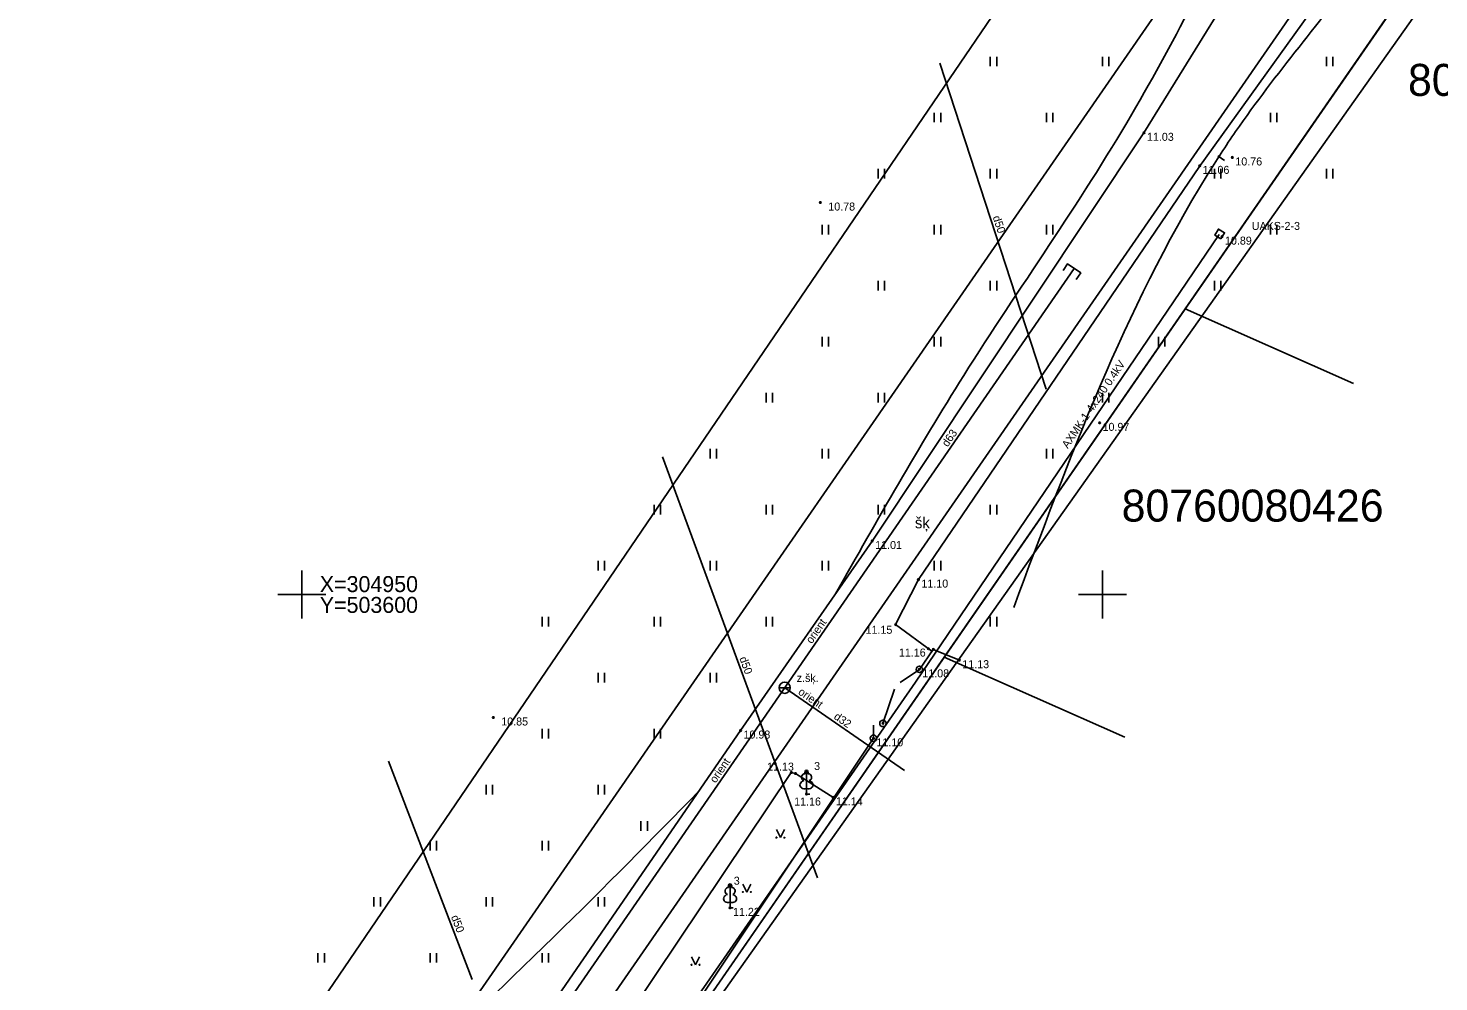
# Model space of a CAD drawing. Extents: x 503353 to 504004, y 304662 to 305049.
# Drawn here: x 503582.9 to 503671, y 304925.8 to 304985.4 of the extents above; entities that cross this region are included whole.
import ezdxf

# ---------------------------------------------------------------- set-up
doc = ezdxf.new("R2010")
doc.units = 0
for name, color, linetype in [('24', 7, 'Continuous'), ('25', 7, 'Continuous'), ('59', 7, 'Continuous'), ('APGR_SARK_####_####_#', 7, 'Continuous'), ('CELI_CAPM_####_####_#', 7, 'Continuous'), ('CELI_CMAL_####_####_#', 7, 'Continuous'), ('CELI_CSEG_####_TKST_#', 7, 'Continuous'), ('DREN_VADP_####_####_#', 7, 'Continuous'), ('DREN_VADP_####_TKST_#', 7, 'Continuous'), ('ELEK_ELEM_####_####_#', 7, 'Continuous'), ('ELEK_VADP_ZSPR_####_#', 7, 'Continuous'), ('ELEK_VADP_ZSPR_TKST_#', 7, 'Continuous'), ('GEOD_ELEM_####_####_#', 7, 'Continuous'), ('GEOD_KORD_####_TKST_#', 7, 'Continuous'), ('NORB_ELEM_####_####_#', 7, 'Continuous'), ('NORB_ZOGS_BARJ_####_#', 7, 'Continuous'), ('NORB_ZOGS_KBST_####_#', 7, 'Continuous'), ('NORB_ZOGS_ZSTP_####_#', 7, 'Continuous'), ('RAMI_UZMR_####_####_#', 7, 'Continuous'), ('RELJ_AATZ_####_TKST_#', 7, 'Continuous'), ('RELJ_ELEM_####_####_#', 7, 'Continuous'), ('RELJ_HORZ_PAMT_####_#', 7, 'Continuous'), ('TERT_DIAM_####_TKST_#', 7, 'Continuous'), ('TERT_ELEM_####_####_#', 7, 'Continuous'), ('UDTK_ELEM_####_####_#', 7, 'Continuous'), ('UDTK_ELEM_####_TKST_#', 7, 'Continuous'), ('UDTK_VADP_UDEN_####_#', 7, 'Continuous'), ('UDTK_VADP_UDEN_TKST_#', 7, 'Continuous')]:
    doc.layers.add(name, color=color, linetype=linetype)

msp = doc.modelspace()

# ---------------------------------------------------------------- linework, layer by layer
at = {"layer": '24'}
for p, q in [((503655.169, 304967.847), (503676.504, 304998.703)), ((503640.119, 304946.083), (503655.169, 304967.847)), ((503665.697, 304963.177), (503655.169, 304967.847)), ((503621.894, 304919.725), (503640.119, 304946.083)), ((503640.119, 304946.083), (503651.401, 304941.078))]:
    msp.add_line(p, q, dxfattribs=at)
at = {"layer": '25'}
msp.add_line((503672.032, 305001.026), (503595.592, 304890.48), dxfattribs=at)
at = {"layer": 'APGR_SARK_####_####_#'}
for p, q in [((503595.509, 304902.665), (503658.316, 304993.498)), ((503669.455, 304988.508), (503606.367, 304897.269))]:
    msp.add_line(p, q, dxfattribs=at)
at = {"layer": 'CELI_CAPM_####_####_#'}
msp.add_lwpolyline([(503630.569, 304938.881), (503619.284, 304922.036)], dxfattribs=at)
at = {"layer": 'CELI_CMAL_####_####_#'}
for points in [[(503605.515, 304909.352), (503607.775, 304912.97), (503627.397, 304941.5), (503635.622, 304953.341), (503652.6, 304978.844), (503660.954, 304992.392), (503665.471, 305000.768), (503665.873, 305004.349)], [(503674.743, 305000.37), (503671.232, 304998.583), (503665.707, 304990.166), (503656.075, 304976.73), (503638.511, 304950.933)], [(503638.511, 304950.933), (503637.086, 304948.12), (503639.351, 304946.45)], [(503630.569, 304938.881), (503630.828, 304938.817), (503633.22, 304937.294)]]:
    msp.add_lwpolyline(points, dxfattribs=at)
at = {"layer": 'DREN_VADP_####_####_#'}
for p, q in [((503646.495, 304962.83), (503639.848, 304983.193)), ((503632.207, 304932.288), (503622.519, 304958.6)), ((503610.64, 304925.952), (503605.409, 304939.594))]:
    msp.add_line(p, q, dxfattribs=at)
at = {"layer": 'ELEK_ELEM_####_####_#'}
msp.add_lwpolyline([(503657.407, 304972.221), (503657.024, 304972.452), (503657.251, 304972.829), (503657.634, 304972.598)], close=True, dxfattribs=at)
at = {"layer": 'ELEK_VADP_ZSPR_####_#'}
msp.add_lwpolyline([(503657.3, 304972.484), (503638.321, 304944.533), (503622.227, 304921.298)], dxfattribs=at)
at = {"layer": 'GEOD_ELEM_####_####_#'}
for p, q in [((503600, 304951.5), (503600, 304950)), ((503600, 304951.5), (503600, 304950)), ((503650, 304951.5), (503650, 304950)), ((503650, 304951.5), (503650, 304950)), ((503598.5, 304950), (503600, 304950)), ((503598.5, 304950), (503600, 304950)), ((503600, 304950), (503600, 304948.5)), ((503600, 304950), (503601.5, 304950)), ((503600, 304950), (503600, 304948.5)), ((503600, 304950), (503601.5, 304950)), ((503648.5, 304950), (503650, 304950)), ((503648.5, 304950), (503650, 304950)), ((503650, 304950), (503650, 304948.5)), ((503650, 304950), (503651.5, 304950)), ((503650, 304950), (503650, 304948.5)), ((503650, 304950), (503651.5, 304950))]:
    msp.add_line(p, q, dxfattribs=at)
at = {"layer": 'NORB_ELEM_####_####_#'}
for centre in [(503638.568, 304945.324), (503636.292, 304941.947), (503635.703, 304941.016)]:
    msp.add_circle(centre, 0.202, dxfattribs=at)
at = {"layer": 'NORB_ZOGS_BARJ_####_#'}
for p, q in [((503638.568, 304945.324), (503637.376, 304944.51)), ((503636.292, 304941.947), (503637.005, 304944.076)), ((503635.703, 304941.016), (503635.703, 304941.839))]:
    msp.add_line(p, q, dxfattribs=at)
at = {"layer": 'NORB_ZOGS_KBST_####_#'}
for points in [[(503639.437, 304946.574), (503638.568, 304945.324)], [(503635.703, 304941.016), (503621.748, 304920.094)]]:
    msp.add_lwpolyline(points, dxfattribs=at)
at = {"layer": 'NORB_ZOGS_ZSTP_####_#'}
msp.add_lwpolyline([(503641.066, 304945.897), (503639.437, 304946.574)], dxfattribs=at)
at = {"layer": 'RAMI_UZMR_####_####_#'}
msp.add_lwpolyline([(503825.923, 304784.828), (503697.433, 304847.709), (503608.51, 304889.842), (503606.524, 304897.202), (503679.244, 304999.942), (503684.897, 305009.76), (503666.777, 305017.939), (503656.134, 304996.39), (503644.103, 304987.6), (503600.987, 304924.263), (503587.985, 304916.668), (503422.237, 304989.372), (503408.615, 305023.495), (503368.776, 305020.183)], dxfattribs=at)
at = {"layer": 'RELJ_ELEM_####_####_#'}
for centre in [(503652.6, 304978.844), (503658.121, 304977.306), (503656.075, 304976.78), (503632.38, 304974.489), (503657.474, 304972.36), (503649.826, 304960.724), (503635.622, 304953.341), (503638.511, 304950.933), (503637.086, 304948.12), (503639.132, 304946.611), (503639.437, 304946.574), (503641.066, 304945.897), (503638.568, 304945.324), (503611.951, 304942.316), (503627.397, 304941.5), (503636.292, 304941.947), (503635.703, 304941.016), (503630.569, 304938.881), (503630.828, 304938.817), (503631.518, 304937.533), (503633.168, 304937.327), (503626.742, 304930.423)]:
    msp.add_circle(centre, 0.05, dxfattribs=at)
at = {"layer": 'RELJ_HORZ_PAMT_####_#'}
msp.add_line((503657.638, 304977.125), (503657.22, 304977.398), dxfattribs=at)
for points in [[(503633.337, 304950.051), (503641.34, 304963.681), (503651.833, 304980), (503659.721, 304994.671), (503662.005, 305000.088), (503662.005, 305002.22), (503658.32, 305004.641)], [(503679.623, 304997.028), (503675.778, 304998.226), (503671.921, 304996.503), (503671.06, 304995.689), (503666.309, 304989.46), (503658.324, 304978.924), (503656.549, 304976.193), (503644.463, 304949.187)], [(503653.856, 304861.224), (503644.002, 304865.053), (503628.506, 304872.58), (503611.965, 304878.986), (503602.441, 304884.188), (503591.366, 304889.404), (503588.291, 304891.572), (503604.352, 304917.909), (503624.778, 304937.692)]]:
    msp.add_spline(points, degree=3, dxfattribs=at)
at = {"layer": 'TERT_ELEM_####_####_#'}
for p, q in [((503643, 304983), (503643, 304983.6)), ((503643.4, 304983), (503643.4, 304983.6)), ((503650, 304983), (503650, 304983.6)), ((503650.4, 304983), (503650.4, 304983.6)), ((503664, 304983), (503664, 304983.6)), ((503664.4, 304983), (503664.4, 304983.6)), ((503639.5, 304979.5), (503639.5, 304980.1)), ((503639.9, 304979.5), (503639.9, 304980.1)), ((503646.5, 304979.5), (503646.5, 304980.1)), ((503646.9, 304979.5), (503646.9, 304980.1)), ((503660.5, 304979.5), (503660.5, 304980.1)), ((503660.9, 304979.5), (503660.9, 304980.1)), ((503636, 304976), (503636, 304976.6)), ((503636.4, 304976), (503636.4, 304976.6)), ((503643, 304976), (503643, 304976.6)), ((503643.4, 304976), (503643.4, 304976.6)), ((503657, 304976), (503657, 304976.6)), ((503657.4, 304976), (503657.4, 304976.6)), ((503664, 304976), (503664, 304976.6)), ((503664.4, 304976), (503664.4, 304976.6)), ((503632.5, 304972.5), (503632.5, 304973.1)), ((503632.9, 304972.5), (503632.9, 304973.1)), ((503639.5, 304972.5), (503639.5, 304973.1)), ((503639.9, 304972.5), (503639.9, 304973.1)), ((503646.5, 304972.5), (503646.5, 304973.1)), ((503646.9, 304972.5), (503646.9, 304973.1)), ((503660.5, 304972.5), (503660.5, 304973.1)), ((503660.9, 304972.5), (503660.9, 304973.1)), ((503636, 304969), (503636, 304969.6)), ((503636.4, 304969), (503636.4, 304969.6)), ((503643, 304969), (503643, 304969.6)), ((503643.4, 304969), (503643.4, 304969.6)), ((503657, 304969), (503657, 304969.6)), ((503657.4, 304969), (503657.4, 304969.6)), ((503632.5, 304965.5), (503632.5, 304966.1)), ((503632.9, 304965.5), (503632.9, 304966.1)), ((503639.5, 304965.5), (503639.5, 304966.1)), ((503639.9, 304965.5), (503639.9, 304966.1)), ((503653.5, 304965.5), (503653.5, 304966.1)), ((503653.9, 304965.5), (503653.9, 304966.1)), ((503629, 304962), (503629, 304962.6)), ((503629.4, 304962), (503629.4, 304962.6)), ((503636, 304962), (503636, 304962.6)), ((503636.4, 304962), (503636.4, 304962.6)), ((503650, 304962), (503650, 304962.6)), ((503650.4, 304962), (503650.4, 304962.6)), ((503625.5, 304958.5), (503625.5, 304959.1)), ((503625.9, 304958.5), (503625.9, 304959.1)), ((503632.5, 304958.5), (503632.5, 304959.1)), ((503632.9, 304958.5), (503632.9, 304959.1)), ((503646.5, 304958.5), (503646.5, 304959.1)), ((503646.9, 304958.5), (503646.9, 304959.1)), ((503622, 304955), (503622, 304955.6)), ((503622.4, 304955), (503622.4, 304955.6)), ((503629, 304955), (503629, 304955.6)), ((503629.4, 304955), (503629.4, 304955.6)), ((503636, 304955), (503636, 304955.6)), ((503636.4, 304955), (503636.4, 304955.6)), ((503643, 304955), (503643, 304955.6)), ((503643.4, 304955), (503643.4, 304955.6)), ((503618.5, 304951.5), (503618.5, 304952.1)), ((503618.9, 304951.5), (503618.9, 304952.1)), ((503625.5, 304951.5), (503625.5, 304952.1)), ((503625.9, 304951.5), (503625.9, 304952.1)), ((503632.5, 304951.5), (503632.5, 304952.1)), ((503632.9, 304951.5), (503632.9, 304952.1)), ((503639.5, 304951.5), (503639.5, 304952.1)), ((503639.9, 304951.5), (503639.9, 304952.1)), ((503615, 304948), (503615, 304948.6)), ((503615.4, 304948), (503615.4, 304948.6)), ((503622, 304948), (503622, 304948.6)), ((503622.4, 304948), (503622.4, 304948.6)), ((503629, 304948), (503629, 304948.6)), ((503629.4, 304948), (503629.4, 304948.6)), ((503643, 304948), (503643, 304948.6)), ((503643.4, 304948), (503643.4, 304948.6)), ((503618.5, 304944.5), (503618.5, 304945.1)), ((503618.9, 304944.5), (503618.9, 304945.1)), ((503625.5, 304944.5), (503625.5, 304945.1)), ((503625.9, 304944.5), (503625.9, 304945.1)), ((503615, 304941), (503615, 304941.6)), ((503615.4, 304941), (503615.4, 304941.6)), ((503622, 304941), (503622, 304941.6)), ((503622.4, 304941), (503622.4, 304941.6)), ((503611.5, 304937.5), (503611.5, 304938.1)), ((503611.9, 304937.5), (503611.9, 304938.1)), ((503618.5, 304937.5), (503618.5, 304938.1)), ((503618.9, 304937.5), (503618.9, 304938.1)), ((503631.518, 304937.88), (503631.518, 304937.533)), ((503631.518, 304937.533), (503631.718, 304937.533)), ((503621.175, 304935.239), (503621.175, 304935.839)), ((503621.575, 304935.239), (503621.575, 304935.839)), ((503629.641, 304935.31), (503629.891, 304934.81)), ((503629.891, 304934.81), (503630.141, 304935.31)), ((503608, 304934), (503608, 304934.6)), ((503608.4, 304934), (503608.4, 304934.6)), ((503615, 304934), (503615, 304934.6)), ((503615.4, 304934), (503615.4, 304934.6)), ((503627.546, 304931.912), (503627.796, 304931.412)), ((503627.796, 304931.412), (503628.046, 304931.912)), ((503604.5, 304930.5), (503604.5, 304931.1)), ((503604.9, 304930.5), (503604.9, 304931.1)), ((503611.5, 304930.5), (503611.5, 304931.1)), ((503611.9, 304930.5), (503611.9, 304931.1)), ((503618.5, 304930.5), (503618.5, 304931.1)), ((503618.9, 304930.5), (503618.9, 304931.1)), ((503626.742, 304930.77), (503626.742, 304930.423)), ((503626.742, 304930.423), (503626.942, 304930.423)), ((503601, 304927), (503601, 304927.6)), ((503601.4, 304927), (503601.4, 304927.6)), ((503608, 304927), (503608, 304927.6)), ((503608.4, 304927), (503608.4, 304927.6)), ((503615, 304927), (503615, 304927.6)), ((503615.4, 304927), (503615.4, 304927.6)), ((503624.341, 304927.367), (503624.591, 304926.867)), ((503624.591, 304926.867), (503624.841, 304927.367))]:
    msp.add_line(p, q, dxfattribs=at)
for points in [[(503631.518, 304939.033), (503631.518, 304937.88)], [(503631.608, 304938.801), (503631.607, 304938.802)], [(503626.742, 304931.923), (503626.742, 304930.77)], [(503626.832, 304931.691), (503626.831, 304931.692)]]:
    msp.add_lwpolyline(points, dxfattribs=at)
for centre, radius in [((503629.641, 304934.809), 0.028), ((503630.141, 304934.809), 0.0263), ((503627.546, 304931.412), 0.028), ((503628.046, 304931.412), 0.0263), ((503624.34, 304926.867), 0.028), ((503624.84, 304926.867), 0.0263)]:
    msp.add_circle(centre, radius, dxfattribs=at)
for centre, major_axis, ratio, start_param, end_param in [((503631.39, 304938.588), (-0.039, -0.212), 0.861323, 3.141593, 6.283185), ((503631.518, 304938.883), (0, -0.15), 0.707107, 3.14537, 5.287485), ((503631.518, 304938.883), (0, -0.15), 0.707107, 0.995701, 3.137816), ((503631.646, 304938.588), (0.039, -0.212), 0.861323, 0, 3.141593), ((503631.428, 304938.126), (0.307, 0.095), 0.814445, 1.570796, 4.752015), ((503631.608, 304938.126), (-0.307, 0.095), 0.814445, 1.531171, 4.712389), ((503626.614, 304931.478), (-0.039, -0.212), 0.861323, 3.141593, 6.283185), ((503626.742, 304931.773), (0, -0.15), 0.707107, 3.14537, 5.287485), ((503626.742, 304931.773), (0, -0.15), 0.707107, 0.995701, 3.137816), ((503626.87, 304931.478), (0.039, -0.212), 0.861323, 0, 3.141593), ((503626.652, 304931.016), (0.307, 0.095), 0.814445, 1.570796, 4.752015), ((503626.832, 304931.016), (-0.307, 0.095), 0.814445, 1.531171, 4.712389)]:
    msp.add_ellipse(centre, major_axis=major_axis, ratio=ratio, start_param=start_param, end_param=end_param, dxfattribs=at)
at = {"layer": 'UDTK_ELEM_####_####_#'}
msp.add_line((503629.803, 304944.175), (503630.506, 304944.175), dxfattribs=at)
msp.add_lwpolyline([(503647.547, 304970.248), (503647.831, 304970.66), (503648.654, 304970.092), (503648.37, 304969.68)], dxfattribs=at)
msp.add_circle((503630.155, 304944.175), 0.351, dxfattribs=at)
at = {"layer": 'UDTK_VADP_UDEN_####_#'}
msp.add_line((503630.155, 304944.175), (503637.634, 304939.011), dxfattribs=at)
msp.add_lwpolyline([(503597.433, 304894.737), (503617.042, 304925.181), (503648.243, 304970.376)], dxfattribs=at)

# ---------------------------------------------------------------- texts
at = {"layer": '59'}
for s, p in [('80760080070', (503669.091, 304981.15)), ('80760080426', (503651.204, 304954.554))]:
    msp.add_text(s, height=2, dxfattribs=at).set_placement(p)
at = {"layer": 'CELI_CSEG_####_TKST_#'}
msp.add_text('šķ', height=0.7, dxfattribs=at).set_placement((503638.289, 304954.134))
at = {"layer": 'DREN_VADP_####_TKST_#'}
for rotation, p in [(288.07827, (503643.143, 304973.582)), (290.21459, (503627.313, 304946.014)), (290.97817, (503609.302, 304929.861))]:
    msp.add_text('d50', height=0.5, rotation=rotation, dxfattribs=at).set_placement(p)
at = {"layer": 'ELEK_VADP_ZSPR_TKST_#'}
msp.add_text('UAKS-2-3', height=0.5, dxfattribs=at).set_placement((503659.335, 304972.777))
msp.add_text('AXMK-1-4x240 0.4kV', height=0.5, rotation=55.82311, dxfattribs=at).set_placement((503647.84, 304959.086))
at = {"layer": 'GEOD_KORD_####_TKST_#'}
for s, p in [('   X=304950', (503600, 304950.15)), ('   Y=503600', (503600, 304948.85))]:
    msp.add_text(s, height=1, dxfattribs=at).set_placement(p)
at = {"layer": 'RELJ_AATZ_####_TKST_#'}
for s, p in [(' 11.03', (503652.6, 304978.344)), (' 10.76', (503658.121, 304976.806)), (' 11.06', (503656.075, 304976.28)), ('10.78', (503632.88, 304973.989)), (' 10.89', (503657.474, 304971.86)), (' 10.97', (503649.826, 304960.224)), (' 11.01', (503635.622, 304952.841)), (' 11.10', (503638.511, 304950.433)), (' 11.15', (503635.022, 304947.546)), (' 11.16', (503637.103, 304946.123)), (' 11.13', (503641.066, 304945.397)), (' 11.08', (503638.568, 304944.824)), ('10.85', (503612.451, 304941.816)), (' 10.98', (503627.397, 304941)), (' 11.10', (503635.703, 304940.516)), (' 11.13', (503628.871, 304938.995)), (' 11.16', (503630.561, 304936.817)), (' 11.14', (503633.168, 304936.827)), (' 11.22', (503626.742, 304929.923))]:
    msp.add_text(s, height=0.5, dxfattribs=at).set_placement(p)
at = {"layer": 'TERT_DIAM_####_TKST_#'}
for p in [(503631.991, 304939.034), (503626.973, 304931.868)]:
    msp.add_text('3', height=0.5, dxfattribs=at).set_placement(p)
at = {"layer": 'UDTK_ELEM_####_TKST_#'}
msp.add_text('z.šķ.', height=0.5, dxfattribs=at).set_placement((503630.907, 304944.537))
at = {"layer": 'UDTK_VADP_UDEN_TKST_#'}
for s, rotation, p in [('d63', 55.38025, (503640.333, 304959.183)), ('orient', 55.38025, (503631.844, 304946.887)), ('orient', 325.38025, (503630.951, 304943.808)), ('d32', 325.38025, (503633.182, 304942.267)), ('orient', 55.38025, (503625.835, 304938.181))]:
    msp.add_text(s, height=0.5, rotation=rotation, dxfattribs=at).set_placement(p)

doc.saveas('drawing.dxf')
